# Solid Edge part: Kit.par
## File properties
Sűrűség: 0,000 kg/m^3
Pontosság: 0,990
Author: ahadarics
Last saved by: ahadarics
Revision: 76
Username: ahadarics
Dokumentum tartalom típus: 0
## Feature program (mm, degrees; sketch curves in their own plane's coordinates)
base feature "unnamed BaseFeature 1"
sketch for "Furat_1" plane through (0, -45, 8.5) normal (0, 0, 1) x-axis (0, 1, 0)
  hole centre (0, 0) bore radius 2.067
hole "Furat_1" nominal diameter 5 finite  ThreadDepth = 4.5 mm
chamfer "Letörés_1" setback 0.5
thread "unnamed Thread 1"
chamfer "Letörés_2" setback 1
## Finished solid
Body 1: solid body, 48 faces, 52 edges, 6 vertices.
  Faces by surface: plane 16, cylinder 14, cone 11, torus 7
  Edges by curve: circle 45, line 6, intersection 1
Bounding box of the edges (mm; curved faces can reach further): 19.000 x 28.500 x 18.100, from (-9.5, -67.5, -9.5) to (9.5, -39, 8.6).
Cylindrical faces by radius (mm): R2.06 x1, R2.067 x1, R3.25 x2, R3.55 x1, R4.5 x1, R4.55 x1, R5.55 x1, R5.6 x1, R6.85 x1, R8 x2, R8.6 x1, R9.5 x1
Conical faces (half-angle, radius in mm at the cone's reference point): 8.8315 deg R4.75 x1, 15 deg R5.55 x1, 20.542 deg R3.55 x1, 24.3997 deg R3.55 x1, 27.3182 deg R3.0335 x1, 29.1112 deg R4.1553 x1, 45 deg R2.567 x1, 45 deg R4.65 x1, 45 deg R4.8 x1, 45 deg R8 x1, 60 deg R7.425 x1
Toroidal faces (ring radius, tube radius in mm): R3.2 r0.2 x1, R3.3 r0.3 x1, R4.3301 r0.2 x1, R4.35 r0.2 x1, R5.35 r0.2 x1, R5.4 r0.2 x2
Planar faces by outward normal: +y 5, +z 2, -y 9
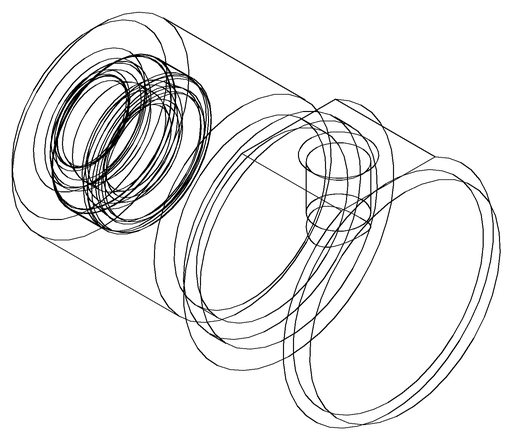
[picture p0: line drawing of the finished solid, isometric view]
